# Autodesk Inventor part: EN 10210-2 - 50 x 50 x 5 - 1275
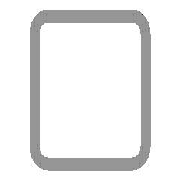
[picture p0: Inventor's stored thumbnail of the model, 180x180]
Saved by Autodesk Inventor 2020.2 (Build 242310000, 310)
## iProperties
Created: 2019-01
Part Number: EN 10210-2 - 50 x 50 x 5 - 1275
Material: Stahl, weich
Description: Rohrleitung
Document SubType Name: Modeling
Standard: DIN
Designer: lutzd
Standard Revision: 2006-07
Standards Organization: DIN
Language: de-DE
Size Designation: 50 x 50 x 5
Categories: <MemberInstance><Categories><Category DisplayName="Profile" InternalName="089c4875-fa83-4c05-b084-43b9cc11f5ed" Mnemonic="GRDR"><CategoryParameter DisplayName="
Stock Number: 50 x 50 x 5
Mass: 8739.39 g
Surface Area: 4333.85 cm^2
Volume: 1113.3 cm^3
Density: 7.85 g/cm^3
Appearance: Semi-Polished(8)
IsCustomPart: 1
G_L: 1275,000 mm
G_W: 50,000 mm
G_H: 50,000 mm
DocNumber: ADSK-014268
Folder: .
Dimensions: 50x50x1275 mm
Mass: 8,739 kg
+CB783A87-5135-4E96-99EC-B1B494DCB73B+SCHNITTDETAIL1: Schnittwinkel 90,00 grd
+BBCD62C2-AF6F-4423-81D0-84BFD8DD7942+SCHNITTDETAIL2: Schnittwinkel 90,00 grd
VLT_Material: Stahl, weich
_CCFamilyMember: 16
_CCFamilyDisplayName: DIN EN 10210-2 (USAS B17.1 quadratisch) - Rohrleitung — In Klammern angegebene Größen wurden aufgehoben
_FrameMemberDoc: Frame Member File
_Version: 15.0.0
_GetPNFromCC: 1
Title: Profil-Bauteil
Author: lutzd
Revision Number: -
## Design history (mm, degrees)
node "Startebene"
node "Endebene"
sketch "Skizze"
  geometry: L1 (-25, -17.5)-(-25, 17.5); L2 (-17.5, 25)-(17.5, 25); L3 (25, 17.5)-(25, -17.5); L4 (17.5, -25)-(-17.5, -25); L5 (-15, 20)-(15, 20); L6 (20, 15)-(20, -15); L7 (15, -20)-(-15, -20); L8 (-20, -15)-(-20, 15); L9 (0, 37.175)-(0, -37.175) reference; L10 (-37.175, 0)-(37.175, 0) reference; A1 r 7.5 centre (-17.5, -17.5) between (-25, -17.5) and (-17.5, -25); A2 r 7.5 centre (-17.5, 17.5) between (-17.5, 25) and (-25, 17.5); A3 r 7.5 centre (17.5, 17.5) between (25, 17.5) and (17.5, 25); A4 r 7.5 centre (17.5, -17.5) between (17.5, -25) and (25, -17.5); A5 r 5 centre (-15, -15) between (-20, -15) and (-15, -20); A6 r 5 centre (-15, 15) between (-15, 20) and (-20, 15); A7 r 5 centre (15, 15) between (20, 15) and (15, 20); A8 r 5 centre (15, -15) between (15, -20) and (20, -15)
  constraints: 16 end point, 16 point on circle, 16 tangent, 8 centre point, 6 equal radius, 4 parallel, 2 perpendicular, 2 other
  dimensions: "d7" = 7.5 radius of A1 (= G_IR); "d10" = 50 distance between parallel lines of L2 L4 (= G_H); "d11" = 50 distance between parallel lines of L1 L3 (= G_W); "d12" = 5 distance between parallel lines of L3 L6 (= G_T); "d15" = 25 distance between parallel lines of L2 L10 (= 0.5 x d10); "d16" = 25 distance between parallel lines of L9 L3 (= 0.5 x d11); "d19" = 5 radius of A5 (= G_T); "d20" = 5 distance between parallel lines of L4 L7 (= G_T)
extrude "Körper" new body sketch "Skizze" stored distance "d3" = 1275 (= G_L); taper "d4" = 0 deg
node "Driven Length"
  sketch "Sketch3"
    geometry: L1 (0, 0)-(10, 0) reference
    constraints: 2 end point, 1 horizontal
  workplane "Work Plane3"
  sketch "Sketch4"
    geometry: L1 (-2, 50)-(12, 50) reference; L2 (-2, 1325)-(12, 1325) reference
    dimensions: "d18" = 1275 distance between parallel lines of L1 L2 (derived)
workplane "Arbeitsebene4"
feature "Trennen1"
workplane "Arbeitsebene5"
feature "Trennen2"
body "Solid1"
other parameters: "G_W" = 50 [user parameter; used in 1 equation term], "G_H" = 50 [user parameter; used in 1 equation term], "G_T" = 5 [user parameter; used in 3 equation terms], "G_IR" = 7.5 [user parameter; used in 1 equation term], "G_L" = 1275 (= d18) [user parameter; used in 1 equation term], "d14" = 1325 (= G_OFFSET_END + B_L), "B_L" = 1375 [user parameter; used in 1 equation term], "d17" = 90 deg
